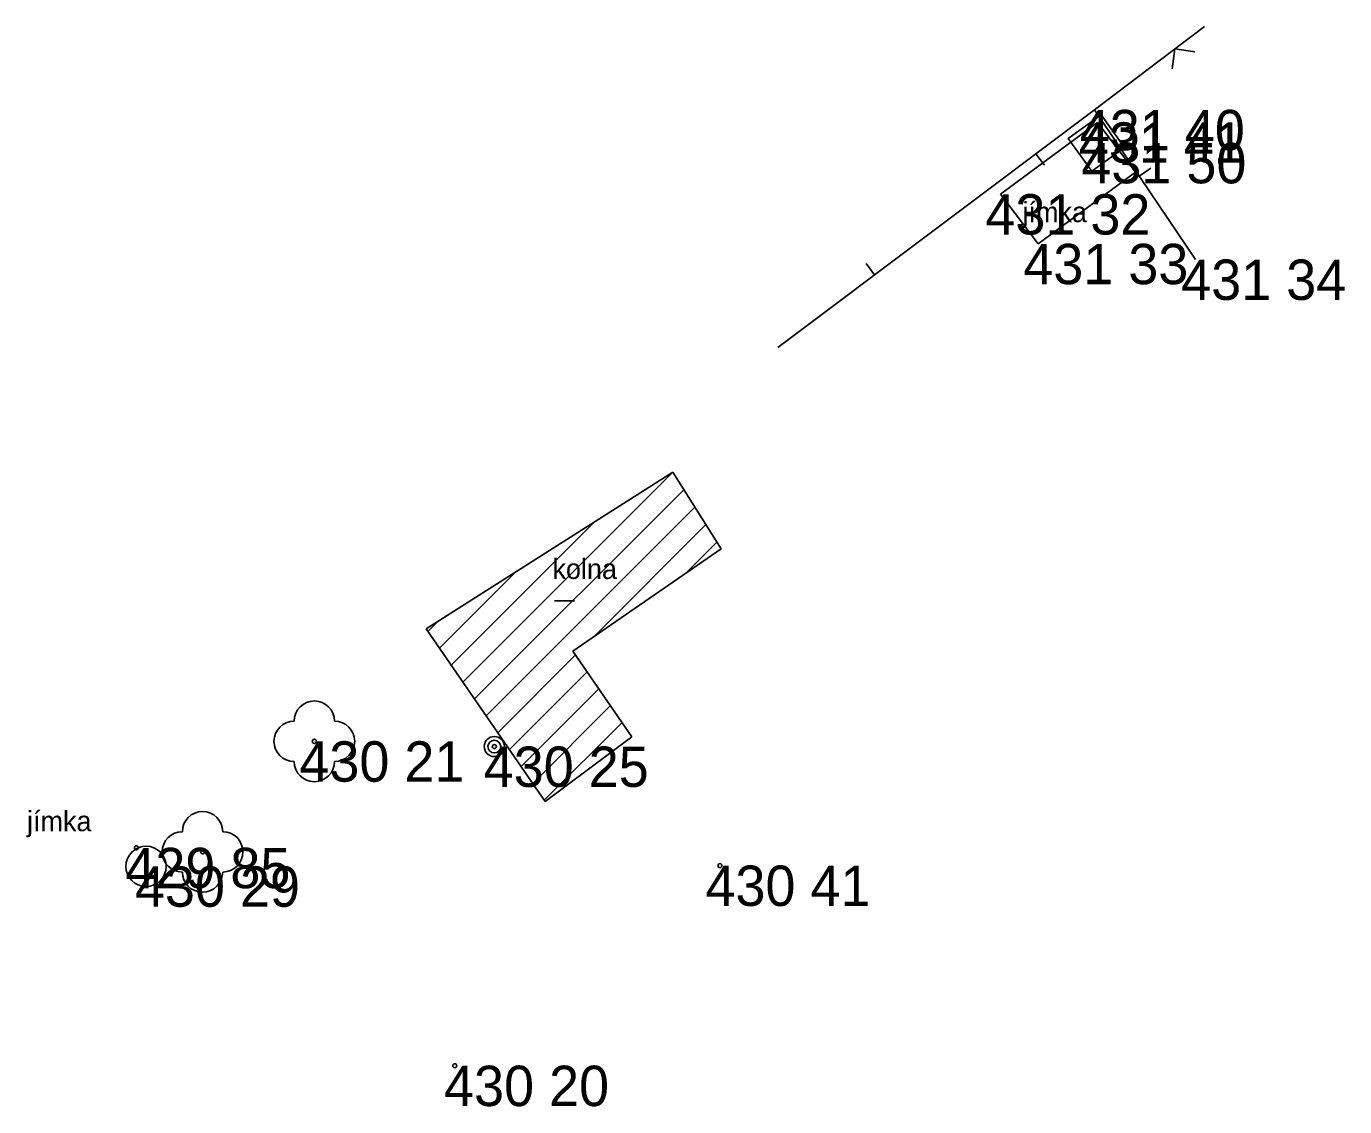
# Model space of a CAD drawing. Extents: x -554123 to -553118, y -1076825 to -1073672.
# Drawn here: x -554049.21 to -554016.54, y -1073821 to -1073794.23 of the extents above; entities that cross this region are included whole.
import ezdxf

# ---------------------------------------------------------------- set-up
doc = ezdxf.new("R2010")
doc.units = 0
for name, color, linetype in [('1', 7, 'Continuous'), ('12', 7, 'Continuous'), ('14', 7, 'Continuous'), ('18', 7, 'Continuous'), ('20', 7, 'Continuous'), ('32', 7, 'Continuous'), ('34', 7, 'Continuous'), ('40', 7, 'Continuous'), ('47', 7, 'Continuous'), ('50', 7, 'Continuous'), ('52', 7, 'Continuous'), ('6', 7, 'Continuous')]:
    doc.layers.add(name, color=color, linetype=linetype)

# ---------------------------------------------------------------- blocks, each defined once
blk = doc.blocks.new('POINT_DISPLAY')
blk.add_line((0, 0), (0, 0))
blk = doc.blocks.new('SA')
at = {"layer": '50'}
blk.add_lwpolyline([(-0.5, -0.5), (0.5, -0.5), (0.5, 0.5), (-0.5, 0.5)], close=True, dxfattribs=at)
blk = doc.blocks.new('T')
at = {"layer": '6'}
blk.add_circle((0, 0), 0.05, dxfattribs=at)
blk = doc.blocks.new('SLB')
at = {"layer": '20'}
for radius in [0.25, 0.158, 0.05]:
    blk.add_circle((0, 0), radius, dxfattribs=at)
blk = doc.blocks.new('STL')
at = {"layer": '34'}
blk.add_circle((0, 0), 0.05, dxfattribs=at)
for centre, start, end in [((0, 0.5), 0, 180), ((-0.5, 0), 90, 270), ((0.5, 0), 270, 90), ((0, -0.5), 180, 0)]:
    blk.add_arc(centre, 0.5, start, end, dxfattribs=at)
blk = doc.blocks.new('BN')
at = {"layer": '47'}
blk.add_line((-0.25, 0), (0.25, 0), dxfattribs=at)
blk = doc.blocks.new('SAK')
at = {"layer": '40'}
blk.add_circle((0, 0), 0.5, dxfattribs=at)

msp = doc.modelspace()

# ---------------------------------------------------------------- linework, layer by layer
at = {"layer": '12'}
for p, q in [((-554022.74, -1073796.3), (-554020.01, -1073794.23)), ((-554020.748, -1073794.79), (-554020.816, -1073795.285)), ((-554020.748, -1073794.79), (-554020.252, -1073794.858)), ((-554030.585, -1073802.191), (-554022.74, -1073796.3)), ((-554020.23, -1073800.01), (-554022.74, -1073796.3)), ((-554024.188, -1073797.387), (-554023.978, -1073797.667)), ((-554021.631, -1073797.939), (-554021.341, -1073797.743)), ((-554028.186, -1073800.39), (-554028.396, -1073800.11))]:
    msp.add_line(p, q, dxfattribs=at)
at = {"layer": '14'}
for p, q in [((-554033.19, -1073805.28), (-554039.3, -1073809.16)), ((-554031.99, -1073807.18), (-554033.19, -1073805.28)), ((-554035.666, -1073809.713), (-554031.99, -1073807.18)), ((-554039.3, -1073809.16), (-554036.35, -1073813.44)), ((-554035.666, -1073809.713), (-554034.2, -1073811.84)), ((-554036.35, -1073813.44), (-554034.2, -1073811.84))]:
    msp.add_line(p, q, dxfattribs=at)
at = {"layer": '18'}
for p, q in [((-554025.07, -1073798.39), (-554022.66, -1073796.61)), ((-554021.72, -1073797.84), (-554022.66, -1073796.61)), ((-554024.13, -1073799.62), (-554021.72, -1073797.84)), ((-554024.13, -1073799.62), (-554025.07, -1073798.39))]:
    msp.add_line(p, q, dxfattribs=at)
at = {"layer": '32'}
for p, q in [((-554038.39, -1073810.48), (-554033.19, -1073805.28)), ((-554038.102, -1073810.899), (-554032.916, -1073805.713)), ((-554037.813, -1073811.317), (-554032.643, -1073806.147)), ((-554038.679, -1073810.062), (-554035.127, -1073806.51)), ((-554035.138, -1073809.349), (-554032.369, -1073806.58)), ((-554032.863, -1073807.782), (-554032.095, -1073807.014)), ((-554038.967, -1073809.643), (-554037.065, -1073807.741)), ((-554039.256, -1073809.224), (-554039.002, -1073808.971)), ((-554037.525, -1073811.736), (-554035.599, -1073809.81)), ((-554037.236, -1073812.154), (-554035.31, -1073810.229)), ((-554036.948, -1073812.573), (-554035.022, -1073810.647)), ((-554036.659, -1073812.992), (-554034.733, -1073811.066)), ((-554036.371, -1073813.41), (-554034.445, -1073811.485))]:
    msp.add_line(p, q, dxfattribs=at)

# ---------------------------------------------------------------- block references
at = {"layer": '1'}
for p in [(-554022.74, -1073796.3), (-554022.66, -1073796.61), (-554022.69, -1073797.12), (-554025.07, -1073798.39), (-554024.13, -1073799.62), (-554020.23, -1073800.01), (-554033.19, -1073805.28), (-554031.99, -1073807.18), (-554039.3, -1073809.16), (-554034.2, -1073811.84), (-554042.07, -1073811.95), (-554037.61, -1073812.08), (-554036.35, -1073813.44), (-554046.48, -1073814.59), (-554044.84, -1073814.69), (-554046.24, -1073815.05), (-554032.02, -1073815.03), (-554038.59, -1073819.99)]:
    msp.add_blockref('POINT_DISPLAY', p, dxfattribs=at)
at = {"layer": '20'}
msp.add_blockref('SLB', (-554037.61, -1073812.08), dxfattribs=at)
at = {"layer": '32'}
msp.add_blockref('POINT_DISPLAY', (-554033.19, -1073805.28), dxfattribs=at)
at = {"layer": '34'}
for p in [(-554042.07, -1073811.95), (-554044.84, -1073814.69)]:
    msp.add_blockref('STL', p, dxfattribs=at)
at = {"layer": '40'}
msp.add_blockref('SAK', (-554046.24, -1073815.05), dxfattribs=at)
at = {"layer": '47'}
msp.add_blockref('BN', (-554035.872, -1073808.472), dxfattribs=at)
at = {"layer": '50', "xscale": 1.0000000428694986, "yscale": 1.0000000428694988, "rotation": 35.68642789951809}
msp.add_blockref('SA', (-554022.69, -1073797.12), dxfattribs=at)
at = {"layer": '6'}
for p in [(-554046.48, -1073814.59), (-554032.02, -1073815.03), (-554038.59, -1073819.99)]:
    msp.add_blockref('T', p, dxfattribs=at)

# ---------------------------------------------------------------- texts
at = {"layer": '52'}
for s, p in [('jímka', (-554024.522, -1073799.083)), ('kolna', (-554036.169, -1073807.926)), ('jímka', (-554049.19, -1073814.178))]:
    msp.add_text(s, height=0.5, dxfattribs=at).set_placement(p)
at = {"layer": '6'}
for s, p in [('431 40 ', (-554023.101, -1073797.3)), ('431 41 ', (-554023.126, -1073797.61)), ('431 50 ', (-554023.063, -1073798.12)), ('431 32 ', (-554025.441, -1073799.39)), ('431 33 ', (-554024.501, -1073800.62)), ('431 34 ', (-554020.589, -1073801.01)), ('430 21 ', (-554042.441, -1073812.95)), ('430 25 ', (-554037.874, -1073813.08)), ('429 85 ', (-554046.754, -1073815.59)), ('430 29 ', (-554046.516, -1073816.05)), ('430 41 ', (-554032.379, -1073816.03)), ('430 20 ', (-554038.856, -1073820.99))]:
    msp.add_text(s, height=1, dxfattribs=at).set_placement(p)

doc.saveas('drawing.dxf')
